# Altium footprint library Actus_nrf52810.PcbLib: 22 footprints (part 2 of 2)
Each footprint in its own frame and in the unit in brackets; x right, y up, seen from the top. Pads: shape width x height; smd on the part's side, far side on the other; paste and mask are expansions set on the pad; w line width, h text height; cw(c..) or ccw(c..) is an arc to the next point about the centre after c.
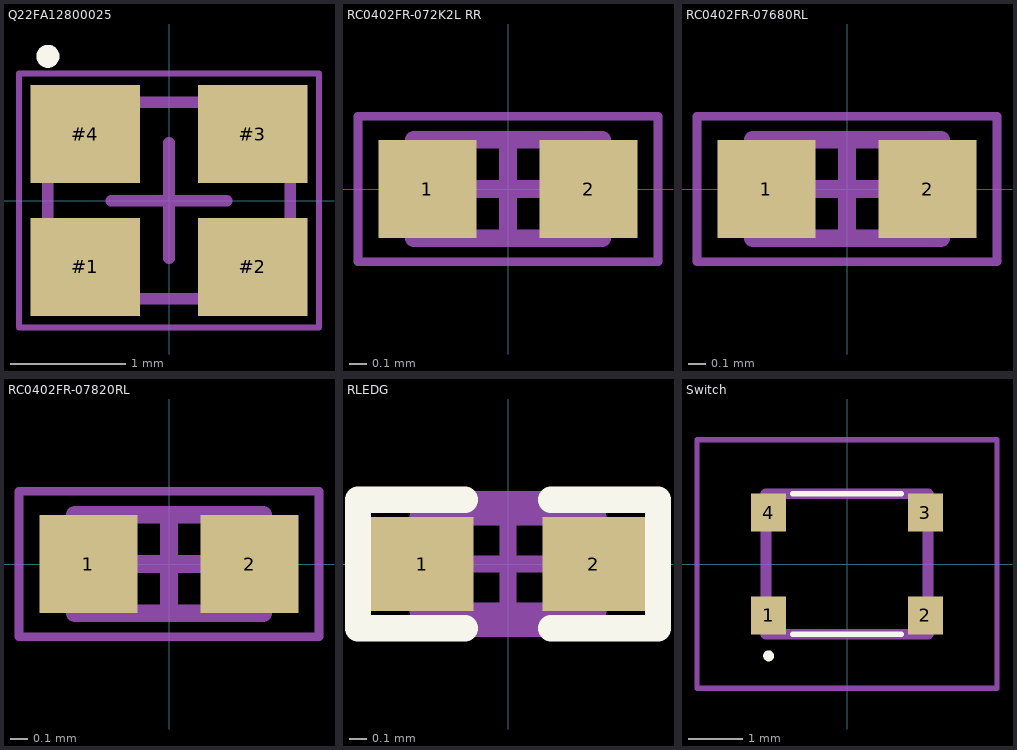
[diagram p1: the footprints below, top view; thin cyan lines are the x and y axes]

## Q22FA12800025 [mm] "X1: 32MHz, XTAL_2016, EPSON"
height 0.5
pads (4):
  rect 0.95x0.85 smd: #1(-0.725,-0.575) #2(0.725,-0.575) #3(0.725,0.575) #4(-0.725,0.575)
Top Overlay:
  circle w0.1: c-1.05,1.25 r0.05
Mechanical 13:
  lines w0.1: -1.05,-0.85 1.05,-0.85 1.05,0.85 -1.05,0.85 -1.05,-0.85
Mechanical 15:
  lines w0.05: -1.3,-1.1 1.3,-1.1 1.3,1.1 -1.3,1.1 -1.3,-1.1
  lines w0.1: -0.5,0 0.5,0 ; 0,-0.5 0,0.5
3D body: height 0.5, standoff 0, extent -1.05,-0.85 1.05,0.85

## RC0402FR-072K2L RR [mm] "RR: 2.2kOhms, 0402, Yageo"
height 0.4
pads (2):
  rect 0.55x0.55 smd: 1(-0.45,0) 2(0.45,0)
Mechanical 13:
  lines w0.1: -0.525,-0.275 0.525,-0.275 0.525,0.275 -0.525,0.275 -0.525,-0.275
Mechanical 15:
  lines w0.05: -0.838,-0.406 0.838,-0.406 0.838,0.406 -0.838,0.406 -0.838,-0.406
  lines w0.1: -0.275,0 0.275,0 ; 0,-0.275 0,0.275
3D body: height 0.4, standoff 0, extent 0.275,-0.275 0.525,0.275
3D body: height 0.4, standoff 0, extent -0.525,-0.275 -0.275,0.275
3D body: height 0.4, standoff 0, extent -0.275,-0.275 0.275,0.275

## RC0402FR-07680RL [mm] "RG: 680 Ohms, 0402, Yageo"
height 0.4
pads (2):
  rect 0.55x0.55 smd: 1(-0.45,0) 2(0.45,0)
Mechanical 13:
  lines w0.1: -0.525,-0.275 -0.525,0.275 0.525,0.275 0.525,-0.275 -0.525,-0.275
Mechanical 15:
  lines w0.05: -0.838,-0.406 -0.838,0.406 0.838,0.406 0.838,-0.406 -0.838,-0.406
  lines w0.1: -0.275,0 0.275,0 ; 0,-0.275 0,0.275
3D body: height 0.4, standoff 0, extent -0.275,-0.275 0.275,0.275
3D body: height 0.4, standoff 0, extent -0.525,-0.275 -0.275,0.275
3D body: height 0.4, standoff 0, extent 0.275,-0.275 0.525,0.275

## RC0402FR-07820RL [mm] "RB: 820 Ohms, 0402, Yageo"
height 0.4
pads (2):
  rect 0.55x0.55 smd: 1(-0.45,0) 2(0.45,0)
Mechanical 13:
  lines w0.1: -0.525,-0.275 -0.525,0.275 0.525,0.275 0.525,-0.275 -0.525,-0.275
Mechanical 15:
  lines w0.05: -0.838,-0.406 -0.838,0.406 0.838,0.406 0.838,-0.406 -0.838,-0.406
  lines w0.1: -0.275,0 0.275,0 ; 0,-0.275 0,0.275
3D body: height 0.4, standoff 0, extent -0.275,-0.275 0.275,0.275
3D body: height 0.4, standoff 0, extent -0.525,-0.275 -0.275,0.275
3D body: height 0.4, standoff 0, extent 0.275,-0.275 0.525,0.275

## RLEDG [mm]
pads (2):
  rect 0.6x0.55 smd: 1(-0.5,0) 2(0.5,0)
Top Overlay:
  lines w0.152: -0.25,-0.375 -0.875,-0.375 -0.875,0.375 -0.25,0.375 ; 0.25,-0.375 0.875,-0.375 0.875,0.375 0.25,0.375
Mechanical 13:
  lines w0.1: -0.525,-0.275 0.525,-0.275 0.525,0.275 -0.525,0.275 -0.525,-0.275
Mechanical 15:
  lines w0.1: -0.275,0 0.275,0 ; 0,-0.275 0,0.275 ; -0.875,-0.375 -0.875,0.375 0.875,0.375 0.875,-0.375 -0.875,-0.375
3D body "User Library-res0402-1.step": height 0.3, standoff 0, extent -0.5,-0.25 0.5,0.25

## Switch [mm] "Switch"
pads (4):
  rect 0.65x0.7 smd: 1(-1.45,-0.95) 2(1.45,-0.95) 3(1.45,0.95) 4(-1.45,0.95)
Top Overlay:
  lines w0.1: -1,-1.3 1,-1.3 ; -1,1.3 1,1.3 ; -1.5,-1.7 ccw(c-1.45,-1.7) -1.4,-1.7 ccw(c-1.45,-1.7) -1.5,-1.7
Mechanical 13:
  lines w0.2: -1.5,-1.3 1.5,-1.3 1.5,1.3 -1.5,1.3 -1.5,-1.3
Mechanical 15:
  lines w0.1: -2.775,-2.3 2.775,-2.3 2.775,2.3 -2.775,2.3 -2.775,-2.3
